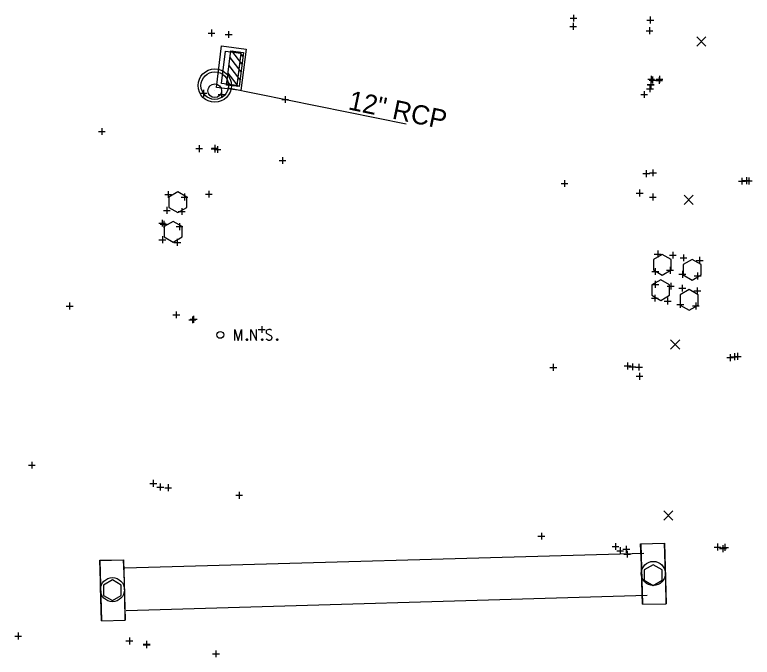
# Model space of a CAD drawing. Extents: x 2188719 to 2189819, y 654569 to 659504.
# Drawn here: x 2189693.7 to 2189801, y 657273.7 to 657367.1 of the extents above; entities that cross this region are included whole.
import ezdxf

# ---------------------------------------------------------------- set-up
doc = ezdxf.new("R2010")
doc.units = 0
for name, color, linetype in [('BR_X_SV_Bottom_of_Beam', 7, 'Continuous'), ('BR_X_SV_Peir', 7, 'Continuous'), ('BR_X_SV_Pier_Cap_Bottom', 7, 'Continuous'), ('BR_X_SV_Pier_Cap_Top', 7, 'Continuous'), ('DR_X_Cells', 7, 'Continuous'), ('DR_X_Elev_Flow', 7, 'Continuous'), ('DR_X_Storm_Sewer', 7, 'Continuous'), ('DR_X_Text', 7, 'Continuous'), ('GK_Drainage_Nodes', 7, 'Continuous'), ('RD_X_Cells', 7, 'Continuous'), ('SV_P_Control_Cells_Set', 7, 'Continuous'), ('SV_X_Random_Point', 7, 'Continuous'), ('SV_X_Shot_Marker', 7, 'Continuous')]:
    doc.layers.add(name, color=color, linetype=linetype)

msp = doc.modelspace()

# ---------------------------------------------------------------- linework, layer by layer
at = {"layer": 'BR_X_SV_Bottom_of_Beam'}
for p, q in [((2189785.21, 657288.78), (2189709.68, 657286.65)), ((2189709.9, 657280.5), (2189785.69, 657282.7))]:
    msp.add_line(p, q, dxfattribs=at)
at = {"layer": 'BR_X_SV_Peir'}
for centre in [(2189786.57, 657285.87), (2189707.89, 657283.51), (2189707.89, 657283.51)]:
    msp.add_circle(centre, 1.75, dxfattribs=at)
at = {"layer": 'BR_X_SV_Pier_Cap_Bottom'}
for p, q in [((2189784.72, 657290.2), (2189788.19, 657290.29)), ((2189784.83, 657287.14), (2189784.72, 657290.2)), ((2189788.3, 657287.23), (2189788.19, 657290.29)), ((2189706.04, 657287.78), (2189709.51, 657287.87)), ((2189706.16, 657284.73), (2189706.04, 657287.78)), ((2189709.63, 657284.82), (2189709.51, 657287.87)), ((2189784.9, 657284.66), (2189784.83, 657287.14)), ((2189788.37, 657284.76), (2189788.3, 657287.23)), ((2189706.22, 657282.25), (2189706.16, 657284.73)), ((2189709.69, 657282.34), (2189709.63, 657284.82)), ((2189784.97, 657281.38), (2189784.9, 657284.66)), ((2189788.44, 657281.47), (2189788.37, 657284.76)), ((2189709.76, 657279.06), (2189709.69, 657282.34)), ((2189706.29, 657278.97), (2189706.22, 657282.25)), ((2189784.97, 657281.38), (2189788.44, 657281.47)), ((2189706.29, 657278.97), (2189709.76, 657279.06))]:
    msp.add_line(p, q, dxfattribs=at)
at = {"layer": 'BR_X_SV_Pier_Cap_Top'}
for p, q in [((2189784.72, 657290.2), (2189784.73, 657290.19)), ((2189784.73, 657290.19), (2189788.2, 657290.28)), ((2189784.73, 657290.19), (2189784.97, 657281.38)), ((2189788.19, 657290.29), (2189788.2, 657290.28)), ((2189788.2, 657290.28), (2189788.44, 657281.47)), ((2189706.04, 657287.78), (2189706.05, 657287.77)), ((2189706.05, 657287.77), (2189709.52, 657287.86)), ((2189706.05, 657287.77), (2189706.29, 657278.97)), ((2189709.51, 657287.87), (2189709.52, 657287.86)), ((2189709.52, 657287.86), (2189709.76, 657279.06)), ((2189784.97, 657281.38), (2189788.44, 657281.47)), ((2189784.97, 657281.38), (2189784.97, 657281.38)), ((2189788.44, 657281.47), (2189788.44, 657281.47)), ((2189706.29, 657278.97), (2189709.76, 657279.06)), ((2189706.29, 657278.97), (2189706.29, 657278.97)), ((2189709.76, 657279.06), (2189709.76, 657279.06))]:
    msp.add_line(p, q, dxfattribs=at)
at = {"layer": 'DR_X_Cells'}
for p, q in [((2189726.72, 657359.96), (2189725.26, 657361.85)), ((2189726.58, 657358.84), (2189724.99, 657360.88)), ((2189726.86, 657361.09), (2189726.38, 657361.71)), ((2189726.44, 657357.72), (2189724.85, 657359.76)), ((2189726.24, 657356.68), (2189724.71, 657358.64)), ((2189725.11, 657356.82), (2189724.57, 657357.52))]:
    msp.add_line(p, q, dxfattribs=at)
for points in [[(2189723.02, 657356.54), (2189723.77, 657362.58), (2189727.33, 657362.13), (2189726.57, 657356.1)], [(2189723.76, 657357.12), (2189724.35, 657361.83), (2189726.59, 657361.55), (2189726, 657356.84)], [(2189724.49, 657356.9), (2189725.11, 657361.86), (2189726.93, 657361.64), (2189726.31, 657356.67)]]:
    msp.add_lwpolyline(points, close=True, dxfattribs=at)
for centre, radius in [((2189722.77, 657356.81), 2.42), ((2189722.77, 657356.81), 2), ((2189722.77, 657356.06), 1)]:
    msp.add_circle(centre, radius, dxfattribs=at)
at = {"layer": 'DR_X_Elev_Flow'}
for p, q in [((2189733.02, 657355.3), (2189733.02, 657354.3)), ((2189732.52, 657354.8), (2189733.52, 657354.8)), ((2189733.02, 657354.8), (2189733.02, 657354.8))]:
    msp.add_line(p, q, dxfattribs=at)
at = {"layer": 'DR_X_Storm_Sewer'}
msp.add_line((2189724.7, 657356.47), (2189750.62, 657351.27), dxfattribs=at)
at = {"layer": 'GK_Drainage_Nodes'}
for p, q in [((2189725.47, 657361.69), (2189725.47, 657361.69)), ((2189722.77, 657358.81), (2189722.77, 657358.81)), ((2189723.4, 657359.56), (2189723.4, 657359.56)), ((2189724.06, 657359.48), (2189724.06, 657359.48)), ((2189724.8, 657359.38), (2189724.8, 657359.38)), ((2189724.8, 657359.38), (2189724.8, 657359.38)), ((2189725.17, 657359.34), (2189725.17, 657359.34)), ((2189726.29, 657359.2), (2189726.29, 657359.2)), ((2189726.95, 657359.11), (2189726.95, 657359.11)), ((2189722.77, 657356.81), (2189722.77, 657356.81)), ((2189722.77, 657356.81), (2189722.77, 657356.81)), ((2189724.88, 657356.98), (2189724.88, 657356.98)), ((2189722.77, 657356.06), (2189722.77, 657356.06)), ((2189722.77, 657354.81), (2189722.77, 657354.81))]:
    msp.add_line(p, q, dxfattribs=at)
msp.add_circle((2189722.77, 657356.81), 2, dxfattribs=at)
at = {"layer": 'RD_X_Cells'}
for points in [[(2189716.11, 657339.11), (2189717.41, 657338.36), (2189718.71, 657339.11), (2189718.71, 657340.61), (2189717.41, 657341.36), (2189716.11, 657340.61), (2189716.11, 657339.11)], [(2189715.43, 657334.81), (2189716.73, 657334.06), (2189718.03, 657334.81), (2189718.03, 657336.31), (2189716.73, 657337.06), (2189715.43, 657336.31), (2189715.43, 657334.81)], [(2189786.57, 657330.02), (2189787.87, 657329.27), (2189789.17, 657330.02), (2189789.17, 657331.52), (2189787.87, 657332.27), (2189786.57, 657331.52), (2189786.57, 657330.02)], [(2189790.91, 657329.28), (2189792.21, 657328.53), (2189793.51, 657329.28), (2189793.51, 657330.78), (2189792.21, 657331.53), (2189790.91, 657330.78), (2189790.91, 657329.28)], [(2189786.34, 657326.32), (2189787.64, 657325.57), (2189788.94, 657326.32), (2189788.94, 657327.82), (2189787.64, 657328.57), (2189786.34, 657327.82), (2189786.34, 657326.32)], [(2189790.48, 657324.89), (2189791.77, 657324.14), (2189793.07, 657324.89), (2189793.07, 657326.39), (2189791.77, 657327.14), (2189790.48, 657326.39), (2189790.48, 657324.89)], [(2189785.25, 657284.89), (2189786.55, 657284.14), (2189787.85, 657284.89), (2189787.85, 657286.39), (2189786.55, 657287.14), (2189785.25, 657286.39), (2189785.25, 657284.89)], [(2189706.58, 657282.67), (2189707.88, 657281.92), (2189709.17, 657282.67), (2189709.17, 657284.17), (2189707.88, 657284.92), (2189706.58, 657284.17), (2189706.58, 657282.67)]]:
    msp.add_lwpolyline(points, dxfattribs=at)
at = {"layer": 'SV_P_Control_Cells_Set'}
for points in [[(2189725.67, 657319.76), (2189725.67, 657321.36), (2189726.17, 657319.76), (2189726.66, 657321.36), (2189726.66, 657319.76)], [(2189728.04, 657319.76), (2189728.04, 657321.36), (2189728.86, 657319.76), (2189728.86, 657321.36)], [(2189731.01, 657321.25), (2189730.99, 657321.27), (2189730.96, 657321.3), (2189730.86, 657321.33), (2189730.74, 657321.36), (2189730.65, 657321.36), (2189730.62, 657321.36), (2189730.47, 657321.32), (2189730.35, 657321.25), (2189730.27, 657321.15), (2189730.25, 657321.04), (2189730.25, 657320.97), (2189730.27, 657320.87), (2189730.36, 657320.78), (2189730.97, 657320.4), (2189731.02, 657320.35), (2189731.05, 657320.3), (2189731.07, 657320.23), (2189731.07, 657320.15), (2189731.06, 657320.07), (2189731.05, 657320.02), (2189731.02, 657319.96), (2189731, 657319.91), (2189730.98, 657319.87), (2189730.95, 657319.84), (2189730.91, 657319.81), (2189730.87, 657319.78), (2189730.84, 657319.77), (2189730.74, 657319.76), (2189730.58, 657319.76), (2189730.48, 657319.78), (2189730.34, 657319.87), (2189730.25, 657319.95)], [(2189727.43, 657319.97), (2189727.49, 657319.97), (2189727.52, 657319.95), (2189727.55, 657319.9), (2189727.55, 657319.84), (2189727.52, 657319.78), (2189727.49, 657319.76), (2189727.43, 657319.76), (2189727.4, 657319.78), (2189727.36, 657319.84), (2189727.36, 657319.9), (2189727.4, 657319.95), (2189727.43, 657319.97)], [(2189729.65, 657319.97), (2189729.7, 657319.97), (2189729.73, 657319.95), (2189729.77, 657319.9), (2189729.77, 657319.84), (2189729.73, 657319.78), (2189729.7, 657319.76), (2189729.65, 657319.76), (2189729.61, 657319.78), (2189729.58, 657319.84), (2189729.58, 657319.9), (2189729.61, 657319.95), (2189729.65, 657319.97)], [(2189731.83, 657319.97), (2189731.88, 657319.97), (2189731.92, 657319.95), (2189731.95, 657319.9), (2189731.95, 657319.84), (2189731.92, 657319.78), (2189731.88, 657319.76), (2189731.83, 657319.76), (2189731.8, 657319.78), (2189731.76, 657319.84), (2189731.76, 657319.9), (2189731.8, 657319.95), (2189731.83, 657319.97)]]:
    msp.add_lwpolyline(points, dxfattribs=at)
msp.add_circle((2189723.58, 657320.56), 0.497, dxfattribs=at)
at = {"layer": 'SV_X_Random_Point'}
for p, q in [((2189792.89, 657362.57), (2189794.22, 657363.9)), ((2189792.89, 657363.9), (2189794.22, 657362.57)), ((2189791.04, 657339.52), (2189792.37, 657340.86)), ((2189791.04, 657340.86), (2189792.37, 657339.52)), ((2189789.09, 657318.5), (2189790.42, 657319.83)), ((2189789.09, 657319.83), (2189790.42, 657318.5)), ((2189788.09, 657293.63), (2189789.42, 657294.96)), ((2189788.09, 657294.96), (2189789.42, 657293.63))]:
    msp.add_line(p, q, dxfattribs=at)
at = {"layer": 'SV_X_Shot_Marker'}
for p, q in [((2189774.96, 657367.12), (2189774.96, 657366.12)), ((2189774.46, 657366.62), (2189775.46, 657366.62)), ((2189774.96, 657366.62), (2189774.96, 657366.62)), ((2189785.62, 657366.35), (2189786.62, 657366.35)), ((2189786.12, 657366.85), (2189786.12, 657365.85)), ((2189786.12, 657366.35), (2189786.12, 657366.35)), ((2189722.3, 657364.95), (2189722.3, 657363.95)), ((2189774.4, 657365.42), (2189775.4, 657365.42)), ((2189774.9, 657365.92), (2189774.9, 657364.92)), ((2189774.9, 657365.42), (2189774.9, 657365.42)), ((2189786.02, 657365.3), (2189786.02, 657364.3)), ((2189721.8, 657364.45), (2189722.8, 657364.45)), ((2189722.3, 657364.45), (2189722.3, 657364.45)), ((2189724.29, 657364.25), (2189725.29, 657364.25)), ((2189724.79, 657364.75), (2189724.79, 657363.75)), ((2189724.79, 657364.25), (2189724.79, 657364.25)), ((2189785.52, 657364.8), (2189786.52, 657364.8)), ((2189786.02, 657364.8), (2189786.02, 657364.8)), ((2189785.76, 657357.75), (2189786.76, 657357.75)), ((2189785.97, 657357.62), (2189786.97, 657357.62)), ((2189786.19, 657357.45), (2189786.19, 657356.45)), ((2189786.26, 657358.25), (2189786.26, 657357.25)), ((2189786.26, 657357.75), (2189786.26, 657357.75)), ((2189786.47, 657358.12), (2189786.47, 657357.12)), ((2189786.47, 657357.62), (2189786.47, 657357.62)), ((2189786.92, 657357.56), (2189787.92, 657357.56)), ((2189786.92, 657357.56), (2189787.92, 657357.56)), ((2189786.96, 657357.73), (2189787.96, 657357.73)), ((2189787.42, 657358.06), (2189787.42, 657357.06)), ((2189787.42, 657358.06), (2189787.42, 657357.06)), ((2189787.42, 657357.56), (2189787.42, 657357.56)), ((2189787.42, 657357.56), (2189787.42, 657357.56)), ((2189787.46, 657358.23), (2189787.46, 657357.23)), ((2189787.46, 657357.73), (2189787.46, 657357.73)), ((2189785.69, 657356.95), (2189786.69, 657356.95)), ((2189785.7, 657356.92), (2189786.7, 657356.92)), ((2189786.08, 657356.85), (2189786.08, 657355.85)), ((2189786.19, 657356.95), (2189786.19, 657356.95)), ((2189786.2, 657357.42), (2189786.2, 657356.42)), ((2189786.2, 657356.92), (2189786.2, 657356.92)), ((2189720.62, 657355.69), (2189721.62, 657355.69)), ((2189721.12, 657356.19), (2189721.12, 657355.19)), ((2189721.12, 657355.69), (2189721.12, 657355.69)), ((2189723.26, 657355.54), (2189724.26, 657355.54)), ((2189723.76, 657356.04), (2189723.76, 657355.04)), ((2189723.76, 657355.54), (2189723.76, 657355.54)), ((2189784.74, 657355.52), (2189785.74, 657355.52)), ((2189785.24, 657356.02), (2189785.24, 657355.02)), ((2189785.24, 657355.52), (2189785.24, 657355.52)), ((2189785.58, 657356.35), (2189786.58, 657356.35)), ((2189786.08, 657356.35), (2189786.08, 657356.35)), ((2189705.85, 657350.13), (2189706.85, 657350.13)), ((2189706.35, 657350.63), (2189706.35, 657349.63)), ((2189706.35, 657350.13), (2189706.35, 657350.13)), ((2189720.51, 657348.15), (2189720.51, 657347.15)), ((2189722.77, 657348.1), (2189722.77, 657347.1)), ((2189722.78, 657348.22), (2189722.78, 657347.22)), ((2189723.17, 657348.02), (2189723.17, 657347.02)), ((2189720.01, 657347.65), (2189721.01, 657347.65)), ((2189720.51, 657347.65), (2189720.51, 657347.65)), ((2189722.27, 657347.6), (2189723.27, 657347.6)), ((2189722.28, 657347.72), (2189723.28, 657347.72)), ((2189722.67, 657347.52), (2189723.67, 657347.52)), ((2189722.77, 657347.6), (2189722.77, 657347.6)), ((2189722.78, 657347.72), (2189722.78, 657347.72)), ((2189723.17, 657347.52), (2189723.17, 657347.52)), ((2189732.12, 657345.92), (2189733.12, 657345.92)), ((2189732.62, 657346.42), (2189732.62, 657345.42)), ((2189732.62, 657345.92), (2189732.62, 657345.92)), ((2189786.51, 657344.62), (2189786.51, 657343.62)), ((2189785.05, 657344.02), (2189786.05, 657344.02)), ((2189785.55, 657344.52), (2189785.55, 657343.52)), ((2189785.55, 657344.02), (2189785.55, 657344.02)), ((2189786.01, 657344.12), (2189787.01, 657344.12)), ((2189786.51, 657344.12), (2189786.51, 657344.12)), ((2189773.14, 657342.57), (2189774.14, 657342.57)), ((2189773.64, 657343.07), (2189773.64, 657342.07)), ((2189773.64, 657342.57), (2189773.64, 657342.57)), ((2189798.96, 657342.92), (2189799.96, 657342.92)), ((2189799.46, 657343.42), (2189799.46, 657342.42)), ((2189799.46, 657342.92), (2189799.46, 657342.92)), ((2189799.61, 657342.99), (2189800.61, 657342.99)), ((2189799.96, 657342.95), (2189800.96, 657342.95)), ((2189800.11, 657343.49), (2189800.11, 657342.49)), ((2189800.11, 657342.99), (2189800.11, 657342.99)), ((2189800.46, 657343.45), (2189800.46, 657342.45)), ((2189800.46, 657342.95), (2189800.46, 657342.95)), ((2189715.99, 657341.47), (2189715.99, 657340.47)), ((2189721.92, 657341.53), (2189721.92, 657340.53)), ((2189784.57, 657341.68), (2189784.57, 657340.68)), ((2189715.49, 657340.97), (2189716.49, 657340.97)), ((2189715.99, 657340.97), (2189715.99, 657340.97)), ((2189717.87, 657340.61), (2189718.87, 657340.61)), ((2189718.37, 657341.11), (2189718.37, 657340.11)), ((2189718.37, 657340.61), (2189718.37, 657340.61)), ((2189721.42, 657341.03), (2189722.42, 657341.03)), ((2189721.92, 657341.03), (2189721.92, 657341.03)), ((2189784.07, 657341.18), (2189785.07, 657341.18)), ((2189784.57, 657341.18), (2189784.57, 657341.18)), ((2189785.99, 657340.6), (2189786.99, 657340.6)), ((2189786.49, 657341.1), (2189786.49, 657340.1)), ((2189786.49, 657340.6), (2189786.49, 657340.6)), ((2189715.3, 657338.67), (2189716.3, 657338.67)), ((2189715.8, 657339.17), (2189715.8, 657338.17)), ((2189715.8, 657338.67), (2189715.8, 657338.67)), ((2189717.46, 657338.51), (2189718.46, 657338.51)), ((2189717.96, 657339.01), (2189717.96, 657338.01)), ((2189717.96, 657338.51), (2189717.96, 657338.51)), ((2189715.13, 657337.31), (2189715.13, 657336.31)), ((2189715.35, 657337.14), (2189715.35, 657336.14)), ((2189714.63, 657336.81), (2189715.63, 657336.81)), ((2189714.85, 657336.64), (2189715.85, 657336.64)), ((2189715.13, 657336.81), (2189715.13, 657336.81)), ((2189715.35, 657336.64), (2189715.35, 657336.64)), ((2189717.14, 657336.31), (2189718.14, 657336.31)), ((2189717.64, 657336.81), (2189717.64, 657335.81)), ((2189717.64, 657336.31), (2189717.64, 657336.31)), ((2189714.66, 657334.4), (2189715.66, 657334.4)), ((2189715.16, 657334.9), (2189715.16, 657333.9)), ((2189715.16, 657334.4), (2189715.16, 657334.4)), ((2189716.82, 657334.01), (2189717.82, 657334.01)), ((2189717.32, 657334.51), (2189717.32, 657333.51)), ((2189717.32, 657334.01), (2189717.32, 657334.01)), ((2189787.21, 657332.82), (2189787.21, 657331.82)), ((2189786.71, 657332.32), (2189787.71, 657332.32)), ((2189787.21, 657332.32), (2189787.21, 657332.32)), ((2189788.91, 657332.15), (2189789.91, 657332.15)), ((2189789.41, 657332.65), (2189789.41, 657331.65)), ((2189789.41, 657332.15), (2189789.41, 657332.15)), ((2189790.46, 657331.77), (2189791.46, 657331.77)), ((2189790.96, 657332.27), (2189790.96, 657331.27)), ((2189790.96, 657331.77), (2189790.96, 657331.77)), ((2189793.3, 657331.9), (2189793.3, 657330.9)), ((2189792.8, 657331.4), (2189793.8, 657331.4)), ((2189793.3, 657331.4), (2189793.3, 657331.4)), ((2189786.35, 657329.78), (2189787.35, 657329.78)), ((2189786.85, 657330.28), (2189786.85, 657329.28)), ((2189786.85, 657329.78), (2189786.85, 657329.78)), ((2189788.5, 657329.96), (2189789.5, 657329.96)), ((2189789, 657330.46), (2189789, 657329.46)), ((2189789, 657329.96), (2189789, 657329.96)), ((2189790.79, 657329.87), (2189790.79, 657328.87)), ((2189793.01, 657329.64), (2189793.01, 657328.64)), ((2189790.29, 657329.37), (2189791.29, 657329.37)), ((2189790.79, 657329.37), (2189790.79, 657329.37)), ((2189792.51, 657329.14), (2189793.51, 657329.14)), ((2189793.01, 657329.14), (2189793.01, 657329.14)), ((2189786.35, 657327.9), (2189787.35, 657327.9)), ((2189786.85, 657328.4), (2189786.85, 657327.4)), ((2189786.85, 657327.9), (2189786.85, 657327.9)), ((2189788.6, 657327.64), (2189789.6, 657327.64)), ((2189789.1, 657328.14), (2189789.1, 657327.14)), ((2189789.1, 657327.64), (2189789.1, 657327.64)), ((2189790.78, 657327.86), (2189790.78, 657326.86)), ((2189792.96, 657327.45), (2189792.96, 657326.45)), ((2189786.78, 657326.41), (2189786.78, 657325.41)), ((2189790.28, 657327.36), (2189791.28, 657327.36)), ((2189790.78, 657327.36), (2189790.78, 657327.36)), ((2189792.46, 657326.95), (2189793.46, 657326.95)), ((2189792.96, 657326.95), (2189792.96, 657326.95)), ((2189786.28, 657325.91), (2189787.28, 657325.91)), ((2189786.78, 657325.91), (2189786.78, 657325.91)), ((2189788.14, 657325.48), (2189789.14, 657325.48)), ((2189788.64, 657325.98), (2189788.64, 657324.98)), ((2189788.64, 657325.48), (2189788.64, 657325.48)), ((2189790.49, 657325.49), (2189790.49, 657324.49)), ((2189792.76, 657325.27), (2189792.76, 657324.27)), ((2189701.16, 657324.75), (2189702.16, 657324.75)), ((2189701.66, 657325.25), (2189701.66, 657324.25)), ((2189701.66, 657324.75), (2189701.66, 657324.75)), ((2189789.99, 657324.99), (2189790.99, 657324.99)), ((2189790.49, 657324.99), (2189790.49, 657324.99)), ((2189792.26, 657324.77), (2189793.26, 657324.77)), ((2189792.76, 657324.77), (2189792.76, 657324.77)), ((2189716.67, 657323.47), (2189717.67, 657323.47)), ((2189717.17, 657323.97), (2189717.17, 657322.97)), ((2189717.17, 657323.47), (2189717.17, 657323.47)), ((2189719.52, 657323.25), (2189719.52, 657322.25)), ((2189719.7, 657323.33), (2189719.7, 657322.33)), ((2189719.02, 657322.75), (2189720.02, 657322.75)), ((2189719.2, 657322.83), (2189720.2, 657322.83)), ((2189719.52, 657322.75), (2189719.52, 657322.75)), ((2189719.7, 657322.83), (2189719.7, 657322.83)), ((2189729.11, 657321.34), (2189730.11, 657321.34)), ((2189729.61, 657321.84), (2189729.61, 657320.84)), ((2189729.61, 657321.34), (2189729.61, 657321.34)), ((2189797.74, 657317.75), (2189797.74, 657316.75)), ((2189798.37, 657317.89), (2189798.37, 657316.89)), ((2189798.83, 657317.93), (2189798.83, 657316.93)), ((2189797.24, 657317.25), (2189798.24, 657317.25)), ((2189797.74, 657317.25), (2189797.74, 657317.25)), ((2189797.87, 657317.39), (2189798.87, 657317.39)), ((2189798.33, 657317.43), (2189799.33, 657317.43)), ((2189798.37, 657317.39), (2189798.37, 657317.39)), ((2189798.83, 657317.43), (2189798.83, 657317.43)), ((2189771.51, 657315.83), (2189772.51, 657315.83)), ((2189772.01, 657316.33), (2189772.01, 657315.33)), ((2189772.01, 657315.83), (2189772.01, 657315.83)), ((2189782.33, 657316.05), (2189783.33, 657316.05)), ((2189782.83, 657316.55), (2189782.83, 657315.55)), ((2189782.83, 657316.05), (2189782.83, 657316.05)), ((2189783.02, 657315.91), (2189784.02, 657315.91)), ((2189783.52, 657316.41), (2189783.52, 657315.41)), ((2189783.52, 657315.91), (2189783.52, 657315.91)), ((2189783.97, 657315.87), (2189784.97, 657315.87)), ((2189784.47, 657316.37), (2189784.47, 657315.37)), ((2189784.47, 657315.87), (2189784.47, 657315.87)), ((2189784.06, 657314.54), (2189785.06, 657314.54)), ((2189784.56, 657315.04), (2189784.56, 657314.04)), ((2189784.56, 657314.54), (2189784.56, 657314.54)), ((2189696.17, 657302.12), (2189696.17, 657301.12)), ((2189695.67, 657301.62), (2189696.67, 657301.62)), ((2189696.17, 657301.62), (2189696.17, 657301.62)), ((2189713.33, 657298.96), (2189714.33, 657298.96)), ((2189713.83, 657299.46), (2189713.83, 657298.46)), ((2189713.83, 657298.96), (2189713.83, 657298.96)), ((2189714.35, 657298.44), (2189715.35, 657298.44)), ((2189714.85, 657298.94), (2189714.85, 657297.94)), ((2189714.85, 657298.44), (2189714.85, 657298.44)), ((2189715.99, 657298.83), (2189715.99, 657297.83)), ((2189715.49, 657298.33), (2189716.49, 657298.33)), ((2189715.99, 657298.33), (2189715.99, 657298.33)), ((2189726.32, 657297.73), (2189726.32, 657296.73)), ((2189725.82, 657297.23), (2189726.82, 657297.23)), ((2189726.32, 657297.23), (2189726.32, 657297.23)), ((2189769.79, 657291.29), (2189770.79, 657291.29)), ((2189770.29, 657291.79), (2189770.29, 657290.79)), ((2189770.29, 657291.29), (2189770.29, 657291.29)), ((2189781.07, 657290.28), (2189781.07, 657289.28)), ((2189782.63, 657289.89), (2189782.63, 657288.89)), ((2189795.9, 657290.21), (2189795.9, 657289.21)), ((2189796.69, 657289.98), (2189796.69, 657288.98)), ((2189796.99, 657290.16), (2189796.99, 657289.16)), ((2189780.57, 657289.78), (2189781.57, 657289.78)), ((2189781.07, 657289.78), (2189781.07, 657289.78)), ((2189781.24, 657289.17), (2189782.24, 657289.17)), ((2189781.74, 657289.67), (2189781.74, 657288.67)), ((2189781.74, 657289.17), (2189781.74, 657289.17)), ((2189782.13, 657289.39), (2189783.13, 657289.39)), ((2189782.63, 657289.39), (2189782.63, 657289.39)), ((2189782.76, 657289.17), (2189782.76, 657288.17)), ((2189795.4, 657289.71), (2189796.4, 657289.71)), ((2189795.9, 657289.71), (2189795.9, 657289.71)), ((2189796.19, 657289.48), (2189797.19, 657289.48)), ((2189796.49, 657289.66), (2189797.49, 657289.66)), ((2189796.69, 657289.48), (2189796.69, 657289.48)), ((2189796.99, 657289.66), (2189796.99, 657289.66)), ((2189782.26, 657288.67), (2189783.26, 657288.67)), ((2189782.76, 657288.67), (2189782.76, 657288.67)), ((2189694.18, 657277.26), (2189694.18, 657276.26)), ((2189693.68, 657276.76), (2189694.68, 657276.76)), ((2189694.18, 657276.76), (2189694.18, 657276.76)), ((2189709.86, 657276.05), (2189710.86, 657276.05)), ((2189710.36, 657276.55), (2189710.36, 657275.55)), ((2189710.36, 657276.05), (2189710.36, 657276.05)), ((2189712.86, 657276.08), (2189712.86, 657275.08)), ((2189712.86, 657276), (2189712.86, 657275)), ((2189712.36, 657275.58), (2189713.36, 657275.58)), ((2189712.36, 657275.5), (2189713.36, 657275.5)), ((2189712.86, 657275.58), (2189712.86, 657275.58)), ((2189712.86, 657275.5), (2189712.86, 657275.5)), ((2189722.45, 657274.18), (2189723.45, 657274.18)), ((2189722.95, 657274.68), (2189722.95, 657273.68)), ((2189722.95, 657274.18), (2189722.95, 657274.18))]:
    msp.add_line(p, q, dxfattribs=at)

# ---------------------------------------------------------------- texts
at = {"layer": 'DR_X_Text'}
msp.add_text('12" RCP', height=2.8, rotation=348.1313, dxfattribs=at).set_placement((2189742.06, 657353.38))

doc.saveas('drawing.dxf')
